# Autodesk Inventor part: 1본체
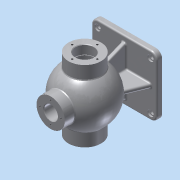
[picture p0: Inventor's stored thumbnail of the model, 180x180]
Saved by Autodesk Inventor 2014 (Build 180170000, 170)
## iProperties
Created: 2017-01
Part Number: 1본체
Material: Aluminum 6061
Document SubType Name: Modeling
Designer: ksu
Density: 2.71 g/cm^3
Appearance: Aluminum - Flat
Mass: 1507.95 g
Surface Area: 1157.96 cm^2
Volume: 556.439 cm^3
Author: ksu
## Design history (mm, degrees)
sketch "Sketch1"
  geometry: L1 (-62.5, 57.5)-(62.5, 57.5); L2 (62.5, 57.5)-(62.5, -57.5); L3 (62.5, -57.5)-(-62.5, -57.5); L4 (-62.5, -57.5)-(-62.5, 57.5); L5 (-62.5, 57.5)-(62.5, -57.5); L6 (62.5, 57.5)-(-62.5, -57.5); 1 further point
  constraints: 12 end point, 2 midpoint, 2 parallel, 1 horizontal, 1 perpendicular
  dimensions: "d0" = 125 distance of L2.end L3.end; "d1" = 115 distance of L1.end L2.end
extrude "Extrusion1" new body sketch "Sketch1" distance "d2" = 10; taper "d3" = 0 deg
sketch "Sketch3"
  geometry: L1 (0, 0)-(0, 85); L2 (51.884, 95.82)-(-51.884, 74.18); A1 r 53 centre (0, 85) between (51.884, 95.82) and (-51.884, 74.18)
  constraints: 4 end point, 2 point on circle, 1 centre point, 1 coincident, 1 midpoint, 1 vertical
  dimensions: "d6" = 85 distance of L1.start L1.end; "d7" = 106 diameter of A1
revolve "Revolution1" sketch "Sketch3" stored, may be unused: angle "d8" = 90 deg
sketch "Sketch4"
  geometry: L1 (62.5, 0)-(-62.5, 0) reference; L2 (-62.5, 10)-(62.5, 10) reference; L3 (-62.5, 0)-(-62.5, 10) reference; L4 (-52.5, 10)-(-31.054, 63.082); L5 (52.5, 10)-(31.054, 63.082); L6 (-31.054, 63.082)-(31.054, 63.082); L7 (-52.5, 10)-(52.5, 10); 1 further point
  constraints: 8 end point, 1 collinear, 1 point on line
  dimensions: "d9" = 22 deg angle of L4 L3; "d10" = 10 distance from line of L3 L4.start
extrude "Extrusion2" join sketch "Sketch4" stored distance "d11" = 8; taper "d12" = 0 deg
sketch "Sketch5"
  geometry: L1 (57.5, 0)-(-57.5, 0) reference; L2 (-57.5, 10)-(57.5, 10) reference; L3 (-57.5, 0)-(-57.5, 10) reference; L4 (-47.5, 10)-(-22.261, 72.468); L5 (47.5, 10)-(22.261, 72.468); L6 (-22.261, 72.468)-(22.261, 72.468); L7 (-47.5, 10)-(47.5, 10); 1 further point
  constraints: 8 end point, 1 collinear, 1 point on line
  dimensions: "d13" = 22 deg angle of L4 L3; "d14" = 10 distance from line of L4.start L3
extrude "Extrusion3" join sketch "Sketch5" stored distance "d15" = 8; taper "d16" = 0 deg
workplane "Work Plane1"
sketch "Sketch6"
  geometry: L1 (62.5, 0)-(-62.5, 0) reference; C1 r 31 at (0, 85); 1 further point
  constraints: 1 centre point
  dimensions: "d19" = 62 diameter of C1
extrude "Extrusion4" join sketch "Sketch6" distance "d20" = 136; taper "d21" = 0 deg
workplane "Work Plane2"
sketch "Sketch7"
  geometry: C1 r 27 at (0, 0); 1 further point
  constraints: 1 centre point, 1 coincident
  dimensions: "d23" = 54 diameter of C1
extrude "Extrusion5" join sketch "Sketch7" distance "d24" = 50; taper "d25" = 0 deg
fillet "Fillet1" dims "d26" = 12
sketch "Sketch8"
  geometry: L1 (62.5, -45.5)-(62.5, 45.5) reference; L2 (50.5, 57.5)-(-50.5, 57.5) reference; L3 (-62.5, 45.5)-(-62.5, -45.5) reference; 5 further points
  dimensions: "d27" = 12 distance from line of L3 point (-50.5, 45.5); "d28" = 12 distance from line of L1 point (50.5, 45.5); "d29" = 12 distance from line of L1 point (50.5, -45.5); "d30" = 12 distance from line of L3 point (-50.5, -45.5); "d31" = 12 distance from line of L2 point (-50.5, 45.5); "d32" = 12 distance from line of L2 point (50.5, 45.5); "d33" = 91 distance of point (50.5, -45.5) point (50.5, 45.5); "d34" = 91 distance of point (-50.5, -45.5) point (-50.5, 45.5)
hole "Hole1" sketch "Sketch8" at (-50.5, 45.5), (50.5, 45.5), (50.5, -45.5), (-50.5, -45.5) diameter "d35" = 8; stored, may be unused: countersink angle "d39" = 90 deg, drill point angle "d41" = 118 deg; dims "d36" = 6, "d37" = 12, "d38" = 3, "d40" = 8
sketch "Sketch9"
  geometry: L1 (-68, 116)-(-68, 54) reference; L2 (68, 116)-(68, 54) reference; L3 (-68, 85)-(68, 85); L4 (-68, 85)-(-18.895, 85); L5 (-18.895, 85)-(-18.895, 102.5); L6 (-39.278, 102.5)-(-68, 102.5); L7 (-68, 102.5)-(-68, 85); L8 (68, 85)-(52, 85); L9 (52, 85)-(52, 102.5); L10 (52, 102.5)-(68, 102.5); L11 (68, 102.5)-(68, 85); L12 (52, 85)-(50.25, 85); L13 (50.25, 85)-(50.25, 103.5); L14 (50.25, 103.5)-(52, 103.5); L15 (52, 103.5)-(52, 85); L16 (50.25, 85)-(28.753, 85); L17 (28.753, 85)-(28.753, 102.5); L18 (28.753, 102.5)-(50.25, 102.5); L19 (50.25, 102.5)-(50.25, 85); A1 r 43 centre (0, 85) between (43, 85) and (-43, 85); 1 further point
  constraints: 34 end point, 8 parallel, 4 horizontal, 4 perpendicular, 3 midpoint, 3 point on circle, 2 point on line, 1 centre point
  dimensions: "d42" = 86 diameter of A1; "d43" = 17.5 distance of L5.end L4.end; "d44" = 16 distance of L9.end L10.end; "d45" = 17.5 distance of L8.end L9.end; "d46" = 1.75 distance of L13.end L14.end; "d47" = 18.5 distance of L12.end L13.end; "d48" = 17.5 distance of L16.end L17.end
revolve "Revolution2" sketch "Sketch9" stored, may be unused: angle "d49" = 90 deg
sketch "Sketch10"
  geometry: C1 r 27 at (0, 0) reference; C2 r 13 at (0, 0)
  constraints: 1 centre point, 1 coincident
  dimensions: "d50" = 26 diameter of C2
extrude "Extrusion6" cut sketch "Sketch10" distance "d51" = 50; taper "d52" = 0 deg
sketch "Sketch11"
  geometry: C1 r 31 at (0, 0) reference; A1 r 24 centre (0, 0) between (0, 24) and (24, 0); 3 further points
  constraints: 4 point on circle, 1 centre point, 1 coincident
  dimensions: "d54" = 48 diameter of A1
hole "Hole2" sketch "Sketch11" at (0, 24), (24, 0), (0, -24), (-24, 0) diameter "d55" = 3.459; stored, may be unused: countersink angle "d59" = 90 deg, drill point angle "d61" = 118 deg; dims "d56" = 16, "d57" = 4, "d58" = 2, "d60" = 19
sketch "Sketch12"
  geometry: C1 r 31 at (0, 0) reference; A1 r 22.5 centre (0, 0) between (0, 22.5) and (-22.5, 0); 3 further points
  constraints: 4 point on circle, 1 centre point, 1 coincident
  dimensions: "d62" = 45 diameter of A1
hole "Hole3" sketch "Sketch12" at (0, 22.5), (-22.5, 0), (0, -22.5), (22.5, 0) diameter "d63" = 3.459; stored, may be unused: countersink angle "d67" = 90 deg, drill point angle "d69" = 118 deg; dims "d64" = 12, "d65" = 4, "d66" = 2, "d68" = 15
workplane "Work Plane3"
sketch "Sketch13"
  geometry: L1 (-20.739, 143.002)-(20.739, 143.002); L2 (20.739, 143.002)-(20.739, 136.998); L3 (20.739, 136.998)-(-20.739, 136.998); L4 (-20.739, 136.998)-(-20.739, 143.002); L5 (27, 150)-(-27, 150) reference; L6 (27, 150)-(27, 130.607) reference; L7 (27, 140)-(0, 140); 1 further point
  constraints: 2 end point, 1 perpendicular, 1 point on line, 2 other
  dimensions: "d71" = 27 distance of L7.start L7.end; "d72" = 10 distance between parallel lines of L7 L5
emboss "Emboss1" sketch "Sketch13" dims "d0" = 125, "d1" = 115, "d9" = 22 deg, "d10" = 10, "d73" = 0.5, "d74" = 0
sketch "Sketch14"
  geometry: C1 r 27 at (0, 0) reference; A1 r 20 centre (0, 0) between (0, 20) and (-20, 0); 2 further points
  constraints: 4 point on circle, 1 centre point, 1 coincident
  dimensions: "d75" = 40 diameter of A1
hole "Hole4" sketch "Sketch14" at (0, 20), (-20, 0), (0, -20), (20, 0) diameter "d76" = 3.459; stored, may be unused: countersink angle "d80" = 90 deg, drill point angle "d82" = 118 deg; dims "d77" = 9, "d78" = 4, "d79" = 2, "d81" = 11
fillet "Fillet2" dims "d83" = 3
fillet "Fillet3" dims "d84" = 3
chamfer "Chamfer1" distance "d85" = 1; stored, may be unused: second distance "d86" = 2, angle "d87" = 45 deg
chamfer "Chamfer2" distance "d88" = 1; stored, may be unused: second distance "d89" = 2, angle "d90" = 45 deg
body "Solid1"
other parameters: "d17" = 68, "d70" = -27
